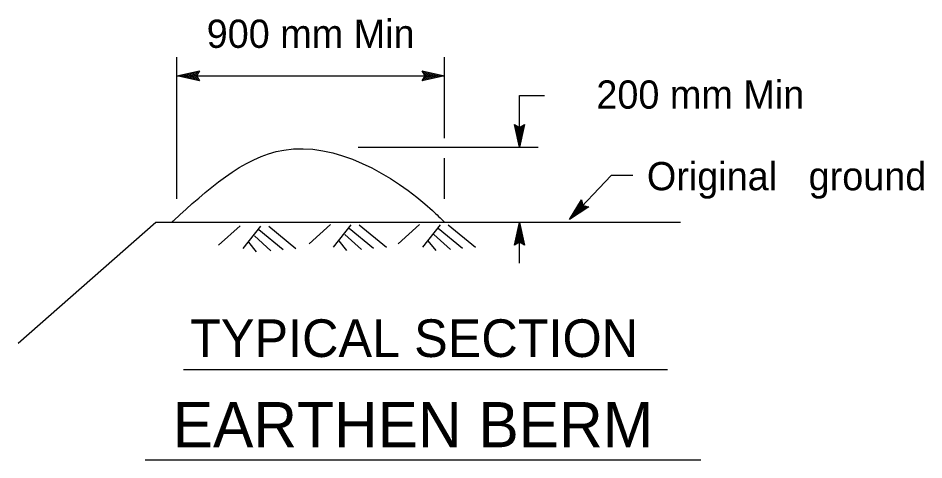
# Model space of a CAD drawing. Extents: x 6707406 to 6714471, y 1868570 to 1872341.
# Drawn here: x 6709481.5 to 6709712.3, y 1869405.3 to 1869517.9 of the extents above; entities that cross this region are included whole.
import ezdxf

# ---------------------------------------------------------------- set-up
doc = ezdxf.new("R2010")
doc.units = 0
for name, color, linetype in [('56 Stg 3 Anno', 7, 'Continuous'), ('57 Undefined', 7, 'Continuous'), ('59 Soundwall Ann', 7, 'Continuous'), ('60 Nongeo Data', 7, 'Continuous')]:
    doc.layers.add(name, color=color, linetype=linetype)

msp = doc.modelspace()

# ---------------------------------------------------------------- linework, layer by layer
at = {"layer": '56 Stg 3 Anno'}
for p, q in [((6709521.95, 1869471.87), (6709521.95, 1869508.01)), ((6709590.2, 1869487.34), (6709590.2, 1869508.01)), ((6709521.95, 1869503.21), (6709527.71, 1869504.49)), ((6709521.95, 1869503.21), (6709590.2, 1869503.21)), ((6709527.71, 1869501.92), (6709521.95, 1869503.21)), ((6709521.95, 1869503.21), (6709521.95, 1869503.21)), ((6709527.51, 1869502.26), (6709523.28, 1869503.21)), ((6709523.29, 1869503.21), (6709527.49, 1869504.14)), ((6709524.61, 1869503.21), (6709527.32, 1869503.81)), ((6709527.28, 1869502.61), (6709524.61, 1869503.21)), ((6709525.93, 1869503.21), (6709527.09, 1869503.46)), ((6709527.11, 1869502.94), (6709525.93, 1869503.21)), ((6709527.71, 1869504.49), (6709526.95, 1869503.21)), ((6709526.95, 1869503.21), (6709527.71, 1869501.92)), ((6709527.71, 1869504.49), (6709527.71, 1869504.49)), ((6709585.21, 1869503.21), (6709584.44, 1869504.5)), ((6709584.44, 1869504.5), (6709584.44, 1869504.5)), ((6709584.44, 1869504.5), (6709590.2, 1869503.21)), ((6709590.2, 1869503.21), (6709584.44, 1869501.93)), ((6709584.44, 1869501.93), (6709585.21, 1869503.21)), ((6709584.65, 1869504.15), (6709588.87, 1869503.21)), ((6709588.86, 1869503.21), (6709584.66, 1869502.28)), ((6709587.55, 1869503.21), (6709584.83, 1869502.61)), ((6709584.87, 1869503.81), (6709587.55, 1869503.21)), ((6709585.04, 1869503.48), (6709586.22, 1869503.21)), ((6709586.22, 1869503.21), (6709585.06, 1869502.96)), ((6709590.2, 1869503.21), (6709590.2, 1869503.21)), ((6709527.71, 1869501.92), (6709527.71, 1869501.92)), ((6709584.44, 1869501.93), (6709584.44, 1869501.93)), ((6709609.25, 1869485.06), (6709609.25, 1869498.24)), ((6709609.25, 1869498.24), (6709615.67, 1869498.24)), ((6709609.25, 1869485.06), (6709607.98, 1869490.82)), ((6709607.98, 1869490.82), (6709607.98, 1869490.82)), ((6709607.98, 1869490.82), (6709609.25, 1869490.05)), ((6709609.25, 1869490.05), (6709610.54, 1869490.82)), ((6709610.54, 1869490.82), (6709609.25, 1869485.06)), ((6709610.54, 1869490.82), (6709610.54, 1869490.82)), ((6709609.25, 1869486.4), (6709608.32, 1869490.6)), ((6709609.26, 1869487.71), (6709608.65, 1869490.43)), ((6709609.26, 1869489.04), (6709609, 1869490.2)), ((6709610.2, 1869490.61), (6709609.25, 1869486.39)), ((6709609.85, 1869490.39), (6709609.26, 1869487.71)), ((6709609.52, 1869490.22), (6709609.26, 1869489.04)), ((6709568.17, 1869485.06), (6709614.05, 1869485.06)), ((6709609.25, 1869485.06), (6709609.25, 1869485.06)), ((6709590.2, 1869471.87), (6709590.2, 1869482.26)), ((6709622.02, 1869466.58), (6709632.64, 1869477.8)), ((6709638.16, 1869477.8), (6709632.64, 1869477.8)), ((6709622.02, 1869466.58), (6709625.05, 1869471.64)), ((6709626.52, 1869469.96), (6709622.93, 1869467.54)), ((6709622.94, 1869467.55), (6709625.15, 1869471.24)), ((6709623.85, 1869468.5), (6709625.27, 1869470.89)), ((6709626.12, 1869470.04), (6709623.85, 1869468.5)), ((6709624.76, 1869469.47), (6709625.37, 1869470.48)), ((6709625.76, 1869470.14), (6709624.76, 1869469.47)), ((6709625.05, 1869471.64), (6709625.05, 1869471.64)), ((6709625.05, 1869471.64), (6709625.45, 1869470.2)), ((6709625.45, 1869470.2), (6709626.92, 1869469.88)), ((6709626.92, 1869469.88), (6709622.02, 1869466.58)), ((6709626.92, 1869469.88), (6709626.92, 1869469.88)), ((6709607.97, 1869460.1), (6709609.25, 1869465.86)), ((6709609.25, 1869465.86), (6709609.25, 1869465.86)), ((6709609.25, 1869465.86), (6709610.53, 1869460.1)), ((6709609.25, 1869455.51), (6709609.25, 1869465.86)), ((6709622.02, 1869466.58), (6709622.02, 1869466.58)), ((6709608.31, 1869460.3), (6709609.25, 1869464.53)), ((6709608.65, 1869460.53), (6709609.25, 1869463.2)), ((6709609.25, 1869463.2), (6709609.85, 1869460.49)), ((6709609.26, 1869464.52), (6709610.19, 1869460.32)), ((6709609.25, 1869460.86), (6709607.97, 1869460.1)), ((6709608.99, 1869460.7), (6709609.25, 1869461.88)), ((6709609.25, 1869461.88), (6709609.51, 1869460.72)), ((6709610.53, 1869460.1), (6709609.25, 1869460.86)), ((6709607.97, 1869460.1), (6709607.97, 1869460.1)), ((6709610.53, 1869460.1), (6709610.53, 1869460.1))]:
    msp.add_line(p, q, dxfattribs=at)
at = {"layer": '57 Undefined'}
for p, q in [((6709523.66, 1869428.34), (6709646.96, 1869428.34)), ((6709513.9, 1869405.34), (6709655.5, 1869405.34))]:
    msp.add_line(p, q, dxfattribs=at)
at = {"layer": '59 Soundwall Ann'}
for p, q in [((6709561.14, 1869465.31), (6709555.66, 1869460.43)), ((6709583.84, 1869465.31), (6709578.36, 1869460.43)), ((6709538.1, 1869464.97), (6709532.62, 1869460.09)), ((6709543.3, 1869464.93), (6709538.78, 1869459.18)), ((6709542.85, 1869464.07), (6709549.04, 1869458.97)), ((6709545.41, 1869464.91), (6709552.33, 1869459.21)), ((6709566.33, 1869465.27), (6709561.82, 1869459.52)), ((6709565.89, 1869464.41), (6709572.08, 1869459.31)), ((6709568.44, 1869465.25), (6709575.37, 1869459.55)), ((6709589.03, 1869465.27), (6709584.52, 1869459.52)), ((6709588.59, 1869464.41), (6709594.78, 1869459.31)), ((6709591.14, 1869465.25), (6709598.06, 1869459.55)), ((6709540.22, 1869460.83), (6709542.2, 1869458.4)), ((6709541.72, 1869462.48), (6709545.95, 1869458.63)), ((6709563.26, 1869461.17), (6709565.24, 1869458.74)), ((6709564.76, 1869462.82), (6709568.98, 1869458.97)), ((6709585.96, 1869461.17), (6709587.94, 1869458.74)), ((6709587.46, 1869462.82), (6709591.68, 1869458.97))]:
    msp.add_line(p, q, dxfattribs=at)
at = {"layer": '60 Nongeo Data'}
for p, q in [((6709516.63, 1869465.86), (6709481.54, 1869435.01)), ((6709650.32, 1869465.86), (6709516.63, 1869465.86))]:
    msp.add_line(p, q, dxfattribs=at)
msp.add_spline([(6709520.62, 1869465.86), (6709521.18, 1869466.37), (6709549.23, 1869484.31), (6709587.12, 1869468.88), (6709590.2, 1869465.94)], degree=3, dxfattribs=at)

# ---------------------------------------------------------------- texts
at = {"layer": '57 Undefined'}
for s, height, p in [('900 mm Min', 7.2, (6709529.58, 1869510.35)), ('200 mm Min', 7.2, (6709628.85, 1869494.86)), ('Original   ground', 7.2002, (6709641.73, 1869474.06)), ('TYPICAL SECTION', 9.6002, (6709525.35, 1869431.56)), ('EARTHEN BERM', 11.5203, (6709520.92, 1869408.56))]:
    msp.add_text(s, height=height, dxfattribs=at).set_placement(p)

doc.saveas('drawing.dxf')
